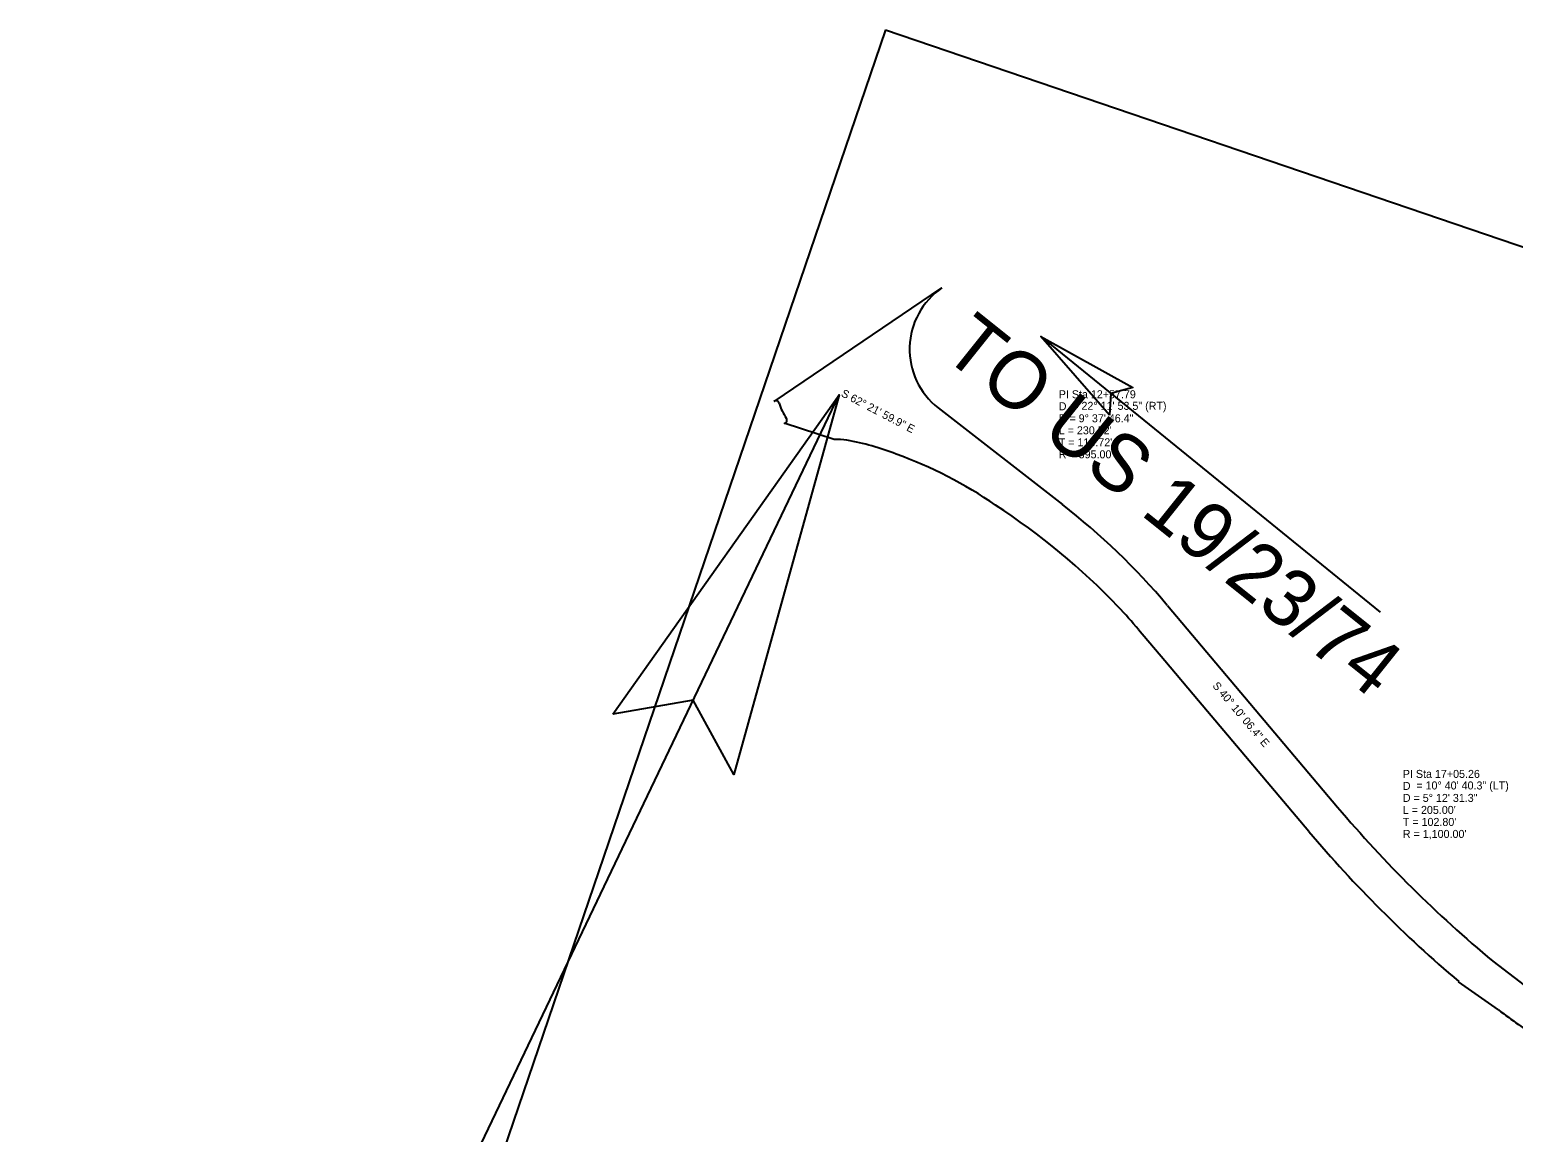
# Model space of a CAD drawing. Extents: x 925297 to 940193, y 663541 to 689899.
# Drawn here: x 927401 to 928699, y 685881 to 686845 of the extents above; entities that cross this region are included whole.
import ezdxf

# ---------------------------------------------------------------- set-up
doc = ezdxf.new("R2010")
doc.units = 0
for name, color, linetype in [('Default', 7, 'Continuous'), ('Exist Horizontal Alignment Curve and Spiral Data', 7, 'Continuous'), ('Exist Horizontal Alignment Direction Label', 7, 'Continuous'), ('Exist Horizontal Alignment Tick Large', 7, 'Continuous'), ('Prop Shade Light', 7, 'Continuous'), ('Prop Terminator CELL', 7, 'Continuous'), ('Sheet Title CELL', 7, 'Continuous')]:
    doc.layers.add(name, color=color, linetype=linetype)

# ---------------------------------------------------------------- blocks, each defined once
blk = doc.blocks.new('Terminator')
at = {"layer": 'Prop Terminator CELL'}
blk.add_lwpolyline([(-9, 1.55), (0, 0), (-9.05, -1.6), (-7.9, 0)], close=True, dxfattribs=at)

msp = doc.modelspace()

# ---------------------------------------------------------------- linework, layer by layer
at = {"layer": 'Default'}
for q in [(927810.6, 685851.5), (929569.2, 686361.5)]:
    msp.add_line((928149.3, 686845.3), q, dxfattribs=at)
at = {"layer": 'Exist Horizontal Alignment Tick Large'}
for p, q in [((928285.4, 686577), (928582.2, 686335.8)), ((927400.8, 685045.9), (928109, 686526.1))]:
    msp.add_line(p, q, dxfattribs=at)
at = {"layer": 'Prop Shade Light'}
for p, q in [((928051.9, 686520.2), (928198.8, 686619.6)), ((928195.5, 686514.5), (928304.2, 686430)), ((928104.5, 686486.9), (928060.9, 686501.1)), ((928396, 686341.8), (928544.9, 686165.4)), ((928393.7, 686293.5), (928370.8, 686320.6)), ((928423.2, 686258.5), (928393.7, 686293.5)), ((928519.7, 686144.2), (928423.2, 686258.5)), ((928680.7, 686030.7), (928726.9, 685995.5)), ((928685.7, 685988.2), (928650.8, 686012.8))]:
    msp.add_line(p, q, dxfattribs=at)
for centre, radius, start, end in [((928235.6, 686565.9), 65.1, 124.4184, 232.0407), ((928053.6, 686517.8), 3, 17.3622, 125.5258), ((928104.6, 686533.7), 50.5, 197.3622, 213.7604), ((928060.2, 686504), 3, 282.8412, 33.7604), ((928108, 686449.1), 38, 78.3782, 95.2874), ((928074.6, 686257.2), 232.8, 68.7974, 79.8236), ((928022.1, 686100.8), 397.7, 55.7702, 69.893), ((927907.9, 685912.6), 617.6, 43.8755, 56.8344), ((927929, 685947.7), 611.1, 40.1684, 52.1254), ((927929, 685947.7), 578.2, 40.1684, 42.8204), ((929373.2, 686864.6), 1083.9, 220.1684, 230.2943), ((929373.2, 686864.6), 1116.8, 220.1684, 229.7018), ((929057.5, 686476.8), 614, 232.7346, 236.7715)]:
    msp.add_arc(centre, radius, start, end, dxfattribs=at)

# ---------------------------------------------------------------- block references
at = {"layer": 'Exist Horizontal Alignment Tick Large', "xscale": 9.999999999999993, "yscale": 9.99999999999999, "rotation": 140.88961525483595}
msp.add_blockref('Terminator', (928285.4, 686577), dxfattribs=at)
at = {"layer": 'Sheet Title CELL', "xscale": 37.50000000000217, "yscale": 37.50000000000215, "rotation": 64.42906465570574}
msp.add_blockref('Terminator', (928109, 686526.1), dxfattribs=at)

# ---------------------------------------------------------------- texts
at = {"layer": 'Default'}
msp.add_text('TO US 19/23/74', height=50, rotation=321.3375, dxfattribs=at).set_placement((928197.4, 686561.2))
at = {"layer": 'Exist Horizontal Alignment Curve and Spiral Data'}
for s, p in [('PI Sta 12+57.79', (928301, 686523)), ('D', (928301, 686512.5)), ('= 22%%d 11\' 53.5" (RT)', (928312.8, 686512.9)), ('D = 9%%d 37\' 46.4"', (928301, 686502)), ("T = 116.72'", (928301, 686481)), ("L = 230.52'", (928301, 686491.5)), ("R = 595.00'", (928301, 686470.5)), ('PI Sta 17+05.26', (928602, 686191)), ('D', (928602, 686180.5)), ('= 10%%d 40\' 40.3" (LT)', (928613.8, 686180.9)), ('D = 5%%d 12\' 31.3"', (928602, 686170)), ("L = 205.00'", (928602, 686159.5)), ("T = 102.80'", (928602, 686149)), ("R = 1,100.00'", (928602, 686138.5))]:
    msp.add_text(s, height=7, dxfattribs=at).set_placement(p)
at = {"layer": 'Exist Horizontal Alignment Direction Label'}
for s, rotation, p in [('S 62%%d 21\' 59.9" E', 332.3666, (928110, 686525.1)), ('S 40%%d 10\' 06.4" E', 310.1684, (928435, 686271.4))]:
    msp.add_text(s, height=7, rotation=rotation, dxfattribs=at).set_placement(p)

doc.saveas('drawing.dxf')
